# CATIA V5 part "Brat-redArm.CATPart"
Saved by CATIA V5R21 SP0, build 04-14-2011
Part number: Brat-redArm
Bounding box of the stored display mesh (mm): x 122 to 162, y -65 to 65, z -64.818 to 64.818
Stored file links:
  C:\Users\MIRCEA\Desktop\PRRO\CATIAV5\Brat-redArm.CATPart
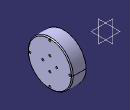
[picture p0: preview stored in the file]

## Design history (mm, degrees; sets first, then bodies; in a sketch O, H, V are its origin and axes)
Body1 (main body)
  Plane1: type Offset, RefPlane yz-plane, Offset 122
  Sketch1 on Plane1, origin (122, 0, 0), H (0, 1, 0), V (0, 0, 1)
    circle A1 centre (0, 0) radius 50
    circle A2 centre (0, 0) radius 65
    radius A1 = 50
    radius A2 = 65
  Pad1: profile Sketch1, direction (1, 0, 0), length 20
  Plane2: type Offset, RefPlane Plane1, Offset 20
  Sketch2 on Plane2, origin (142, 0, 0), H (0, 1, 0), V (0, 0, 1)
    circle A1 centre (0, 0) radius 65
    radius A1 = 65
  Pad2: profile Sketch2, direction (1, 0, 0), length 20
  Plane3: type Offset, RefPlane Plane2, Offset 20
  Sketch3 on Plane3, origin (162, 0, 0), H (0, 1, 0), V (0, 0, 1)
    circle A1 centre (0, 58) radius 3
    circle A2 centre (58, 0) radius 3
    circle A3 centre (0, -58) radius 3
    circle A4 centre (-58, 0) radius 3
    radius A1 = 3
    radius A2 = 3
    radius A3 = 3
    radius A4 = 3
  Pocket1: profile Sketch3, direction (-1, 0, 0), through (limit type 6)
  Chamfer1: length 2.5, angle 45, on edge [face of Pad2 | end face of Pad2]
  Sketch4 on Plane3, origin (162, 0, 0), H (0, 1, 0), V (0, 0, 1)
    circle A1 centre (0, 20) radius 3
    circle A2 centre (20, 0) radius 3
    circle A3 centre (0, -20) radius 3
    circle A4 centre (-20, 0) radius 3
    radius A1 = 3
    radius A2 = 3
    radius A3 = 3
    radius A4 = 3
  Pocket2: profile Sketch4, direction (-1, 0, 0), through (limit type 6)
